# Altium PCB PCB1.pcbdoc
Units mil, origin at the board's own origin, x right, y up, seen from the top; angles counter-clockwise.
Board outline 7744.96 x 4259.33 mil, 2 copper layers (Top Layer, Bottom Layer); 28 components, 7 nets, 68 pads, 56 vias.
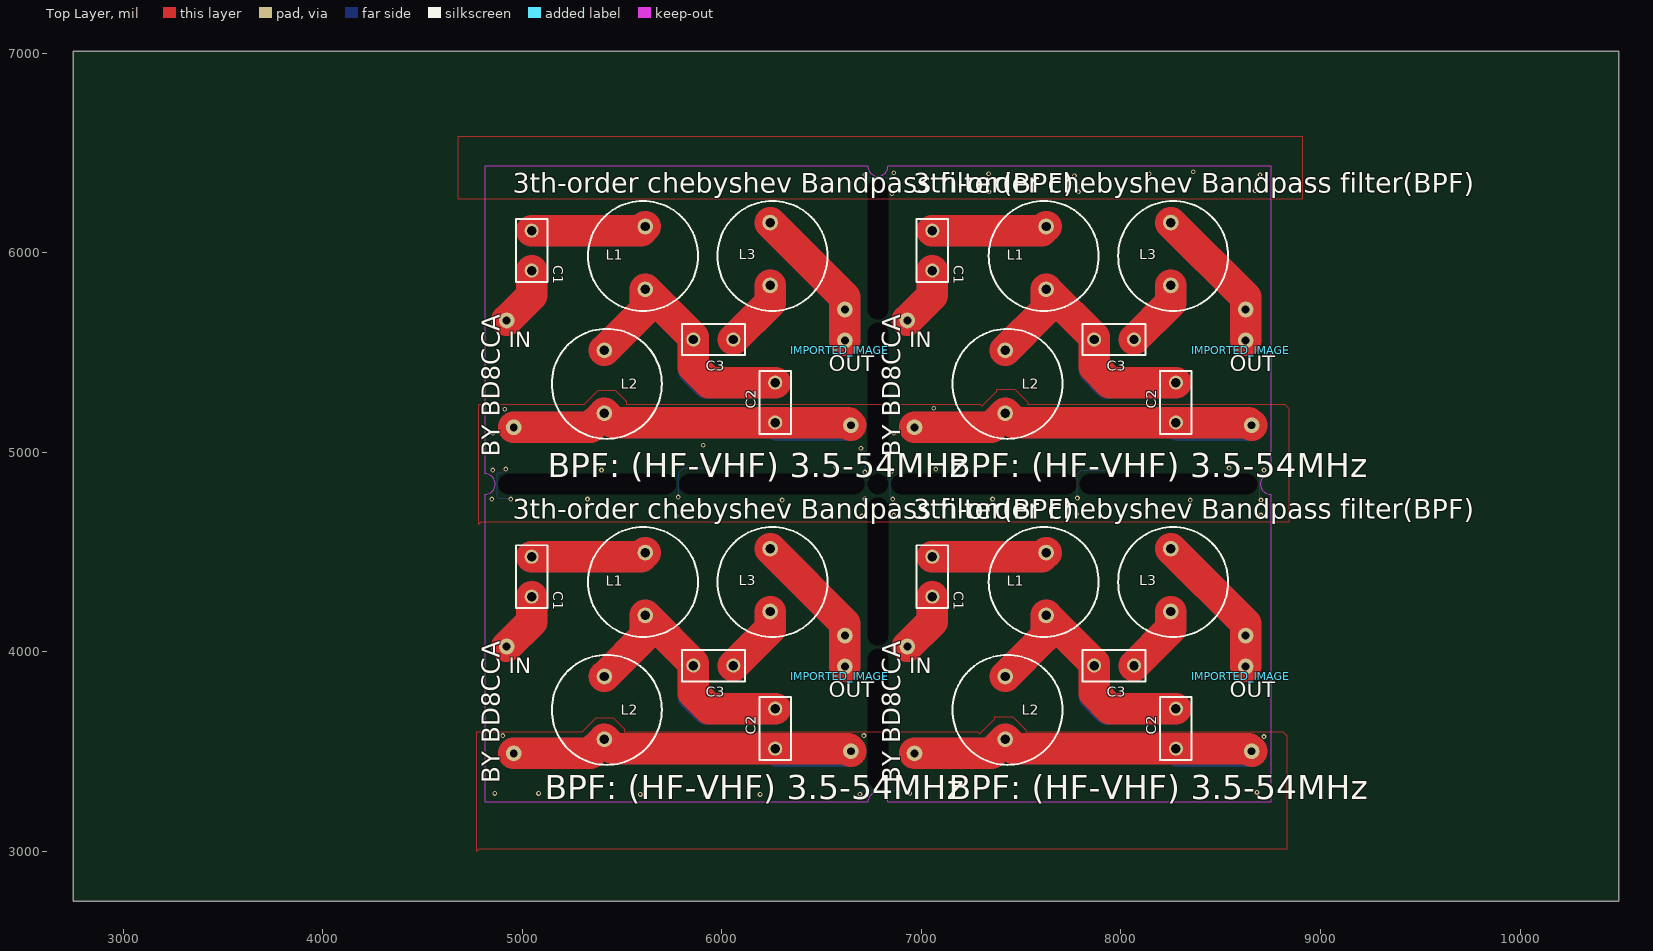
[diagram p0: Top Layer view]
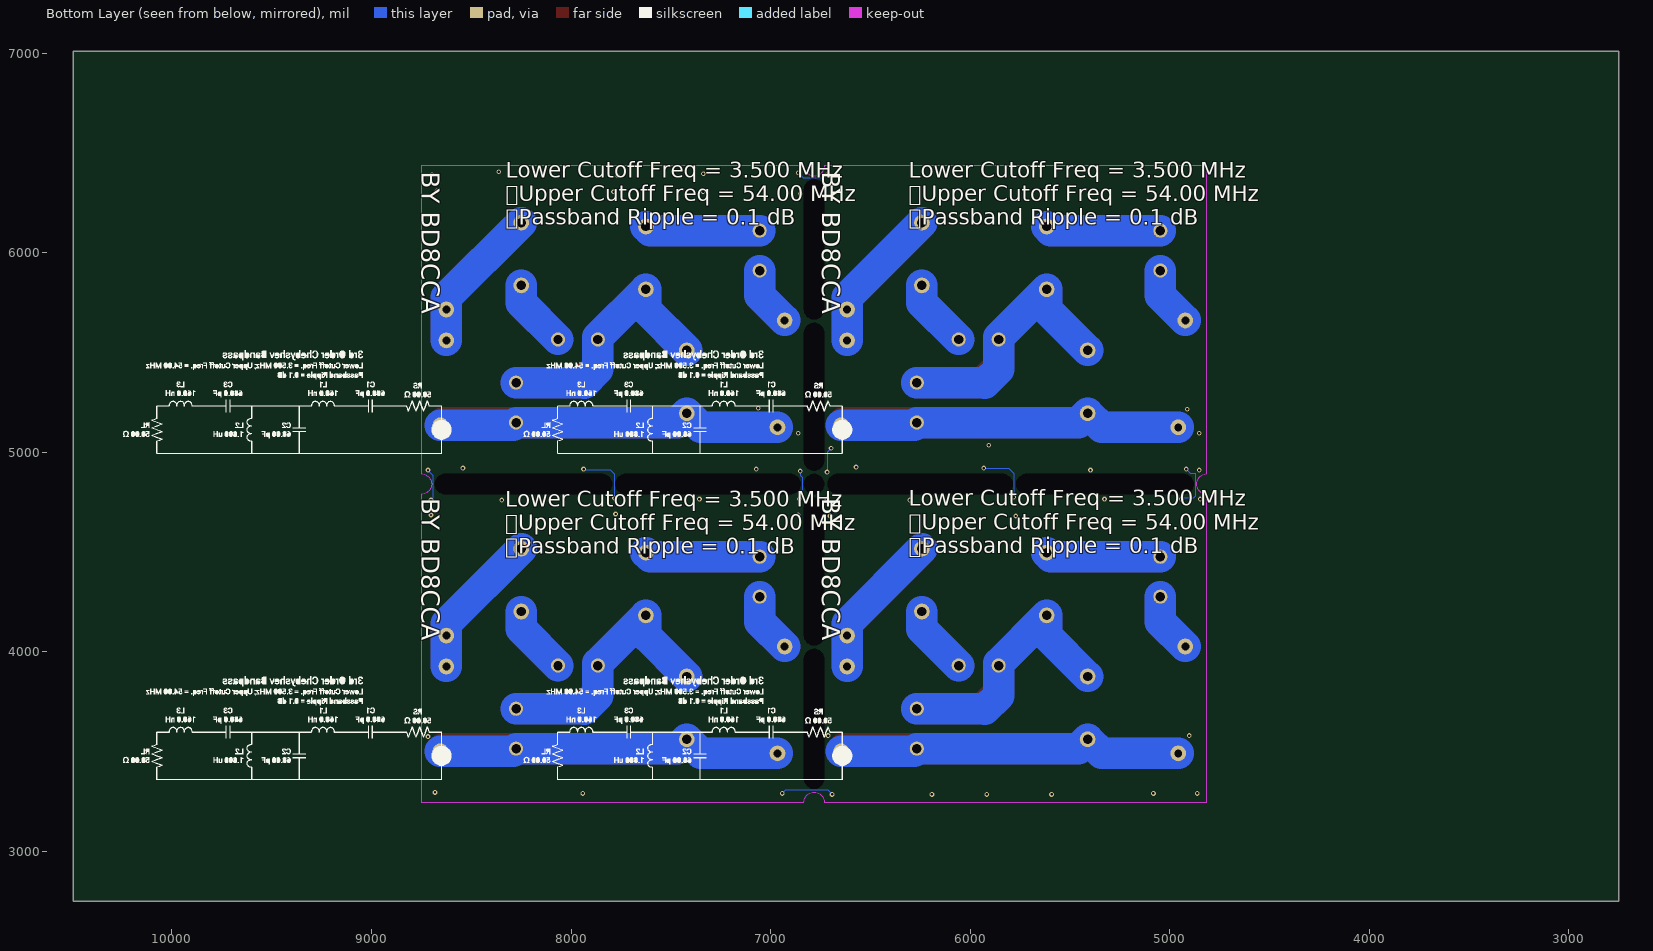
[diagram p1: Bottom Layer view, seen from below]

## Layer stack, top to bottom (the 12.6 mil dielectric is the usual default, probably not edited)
Top Layer: signal copper (thickness not stored)
Dielectric: dielectric 12.6, FR-4, Dk 4.8
Bottom Layer: signal copper (thickness not stored)

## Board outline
10494.96,2750 2750,2750 2750,7009.33 10494.96,7009.33
cut-out: 4931.7,4891.18 ccw(c4931.7,4840) 4880.52,4840 ccw(c4931.7,4840) 4931.7,4788.82 5719.1,4788.82 ccw(c5719.1,4840) 5770.28,4840 ccw(c5719.1,4840) 5719.1,4891.18
cut-out: 5837.21,4891.18 ccw(c5837.21,4840) 5786.03,4840 ccw(c5837.21,4840) 5837.21,4788.82 6663.98,4788.82 ccw(c6663.98,4840) 6715.16,4840 ccw(c6663.98,4840) 6663.98,4891.18
cut-out: 6730.91,6316.38 6730.91,5715.98 ccw(c6782.09,5715.98) 6782.09,5664.8 ccw(c6782.09,5715.98) 6833.27,5715.98 6833.27,6316.38 ccw(c6782.09,6316.38) 6782.09,6367.56 ccw(c6782.09,6316.38)
cut-out: 6730.91,4958.11 ccw(c6782.09,4958.11) 6782.09,4906.93 ccw(c6782.09,4958.11) 6833.27,4958.11 6833.27,5597.87 ccw(c6782.09,5597.87) 6782.09,5649.05 ccw(c6782.09,5597.87) 6730.91,5597.87
cut-out: 6730.91,4082.13 ccw(c6782.09,4082.13) 6782.09,4030.95 ccw(c6782.09,4082.13) 6833.27,4082.13 6833.27,4721.89 ccw(c6782.09,4721.89) 6782.09,4773.07 ccw(c6782.09,4721.89) 6730.91,4721.89
cut-out: 6730.91,4840 ccw(c6782.09,4840) 6782.09,4788.82 ccw(c6782.09,4840) 6833.27,4840 ccw(c6782.09,4840) 6782.09,4891.18 ccw(c6782.09,4840)
cut-out: 7845.08,4891.18 ccw(c7845.08,4840) 7793.9,4840 ccw(c7845.08,4840) 7845.08,4788.82 8632.48,4788.82 ccw(c8632.48,4840) 8683.66,4840 ccw(c8632.48,4840) 8632.48,4891.18
cut-out: 6730.91,3363.62 ccw(c6782.09,3363.62) 6782.09,3312.44 ccw(c6782.09,3363.62) 6833.27,3363.62 6833.27,3964.02 ccw(c6782.09,3964.02) 6782.09,4015.2 ccw(c6782.09,3964.02) 6730.91,3964.02
cut-out: 6900.2,4891.18 ccw(c6900.2,4840) 6849.02,4840 ccw(c6900.2,4840) 6900.2,4788.82 7726.97,4788.82 ccw(c7726.97,4840) 7778.15,4840 ccw(c7726.97,4840) 7726.97,4891.18

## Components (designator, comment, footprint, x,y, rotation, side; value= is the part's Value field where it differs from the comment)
C1 "CT81-M7Y5P1B821KSE" CAP-TH_L8.0-W4.0-P5.00-D1.2 5047.09,6010 r270 top
C1 "CT81-M7Y5P1B821KSE" CAP-TH_L8.0-W4.0-P5.00-D1.2 7054.96,6010 r270 top
C1 "CT81-M7Y5P1B821KSE" CAP-TH_L8.0-W4.0-P5.00-D1.2 5047.09,4376.15 r270 top
C1 "CT81-M7Y5P1B821KSE" CAP-TH_L8.0-W4.0-P5.00-D1.2 7054.96,4376.14 r270 top
C2 "CT81-M7Y5P1B821KSE" CAP-TH_L8.0-W4.0-P5.00-D1.2 6267.84,5248.41 r90 top
C2 "CT81-M7Y5P1B821KSE" CAP-TH_L8.0-W4.0-P5.00-D1.2 8275.71,5248.41 r90 top
C2 "CT81-M7Y5P1B821KSE" CAP-TH_L8.0-W4.0-P5.00-D1.2 6267.84,3614.55 r90 top
C2 "CT81-M7Y5P1B821KSE" CAP-TH_L8.0-W4.0-P5.00-D1.2 8275.71,3614.55 r90 top
C3 "CT81-M7Y5P1B821KSE" CAP-TH_L8.0-W4.0-P5.00-D1.2 5957.84,5564.49 r180 top
C3 "CT81-M7Y5P1B821KSE" CAP-TH_L8.0-W4.0-P5.00-D1.2 7965.71,5564.49 r180 top
C3 "CT81-M7Y5P1B821KSE" CAP-TH_L8.0-W4.0-P5.00-D1.2 5957.84,3930.63 r180 top
C3 "CT81-M7Y5P1B821KSE" CAP-TH_L8.0-W4.0-P5.00-D1.2 7965.71,3930.63 r180 top
IMPORTED_IMAGE "IMPORTED_IMAGE" IMPORTED_IMAGE 6592.09,5510 r0 top
IMPORTED_IMAGE "IMPORTED_IMAGE" IMPORTED_IMAGE 8599.96,5510 r0 top
IMPORTED_IMAGE "IMPORTED_IMAGE" IMPORTED_IMAGE 6592.09,3876.14 r0 top
IMPORTED_IMAGE "IMPORTED_IMAGE" IMPORTED_IMAGE 8599.96,3876.14 r0 top
L1 "直插电感8mm" 直插电感8mm 5617.09,6130.83 r270 top
L1 "直插电感8mm" 直插电感8mm 7624.96,6130.83 r270 top
L1 "直插电感8mm" 直插电感8mm 5617.09,4496.98 r270 top
L1 "直插电感8mm" 直插电感8mm 7624.96,4496.97 r270 top
L2 "直插电感8mm" 直插电感8mm 5412.09,5195 r90 top
L2 "直插电感8mm" 直插电感8mm 7419.96,5195 r90 top
L2 "直插电感8mm" 直插电感8mm 5412.09,3561.14 r90 top
L2 "直插电感8mm" 直插电感8mm 7419.96,3561.14 r90 top
L3 "直插电感8mm" 直插电感8mm 6242.09,5835.55 r90 top
L3 "直插电感8mm" 直插电感8mm 8249.96,5835.55 r90 top
L3 "直插电感8mm" 直插电感8mm 6242.09,4201.69 r90 top
L3 "直插电感8mm" 直插电感8mm 8249.96,4201.69 r90 top

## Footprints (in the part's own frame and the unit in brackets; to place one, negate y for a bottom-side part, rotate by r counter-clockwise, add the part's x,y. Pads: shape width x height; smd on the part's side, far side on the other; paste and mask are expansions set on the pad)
CAP-TH_L8.0-W4.0-P5.00-D1.2 [mm]
  round 1.8 hole 1.2 mask+0.051: 1(-2.54,0) 2(2.54,0)
  silkscreen extent -4,-2 4,2
IMPORTED_IMAGE [mil]
直插电感8mm [mm]
  round 2 hole 1.2 paste+0 mask+0.102: 1(0,0) 2(8,0)
  silkscreen extent -3.25,-7.3 10.75,6.7

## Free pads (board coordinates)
  round 78.74 hole 39.37 mask+2.01: 3(4922.09,4026.14) 3(4922.09,5660) 3(6617.09,3926.14) 3(6617.09,4081.14) 3(6617.09,5560) 3(6617.09,5715) 3(6929.96,4026.14) 3(6929.96,5660) 3(8624.96,3926.14) 3(8624.96,4081.14) 3(8624.96,5560) 3(8624.96,5715) 4(4957.84,3490.63) 4(4957.84,5124.49) 4(6647.09,3501.14) 4(6647.09,5135) 4(6965.71,3490.63) 4(6965.71,5124.49) 4(8654.96,3501.14) 4(8654.96,5135)

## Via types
v1: diameter 24.02, hole 12.01, Top Layer to Bottom Layer, 56 vias

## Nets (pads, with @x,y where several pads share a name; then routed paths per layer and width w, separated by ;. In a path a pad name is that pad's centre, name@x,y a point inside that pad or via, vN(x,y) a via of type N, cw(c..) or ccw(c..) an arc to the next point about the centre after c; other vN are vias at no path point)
$1N347: C1.1 L1.1 | length 4629
  Top Layer w157.5: C1.1@5047.09,4476.15 5596.26,4476.15 L1.1@5617.09,4496.98 ; C1.1@5047.09,6110 5596.26,6110 L1.1@5617.09,6130.83 ; C1.1@7054.96,4476.14 7604.13,4476.14 L1.1@7624.96,4496.97 ; C1.1@7054.96,6110 7604.13,6110 L1.1@7624.96,6130.83
  Bottom Layer w157.5: C1.1@5047.09,4476.15 5596.26,4476.15 L1.1@5617.09,4496.98 ; C1.1@5047.09,6110 5596.26,6110 L1.1@5617.09,6130.83 ; C1.1@7054.96,4476.14 7604.13,4476.14 L1.1@7624.96,4496.97 ; C1.1@7054.96,6110 7604.13,6110 L1.1@7624.96,6130.83
$1N349: C3.1 L3.1 | length 2779
  Top Layer w157.5: C3.1@6057.84,3930.63 6242.09,4114.88 L3.1@6242.09,4201.69 ; C3.1@6057.84,5564.49 6242.09,5748.74 L3.1@6242.09,5835.55 ; C3.1@8065.71,3930.63 8249.96,4114.88 L3.1@8249.96,4201.69 ; C3.1@8065.71,5564.49 8249.96,5748.74 L3.1@8249.96,5835.55
  Bottom Layer w157.5: C3.1@6057.84,3930.63 6242.09,4114.88 L3.1@6242.09,4201.69 ; C3.1@6057.84,5564.49 6242.09,5748.74 L3.1@6242.09,5835.55 ; C3.1@8065.71,3930.63 8249.96,4114.88 L3.1@8249.96,4201.69 ; C3.1@8065.71,5564.49 8249.96,5748.74 L3.1@8249.96,5835.55
$1N351: C2.2 C3.2 L1.2 L2.2 | length 10615.4
  Top Layer w157.5: L2.2@5412.09,3876.11 5617.09,4081.11 5617.09,4182.02 5857.84,3941.26 5857.84,3930.63 5857.84,3793.8 5937.09,3714.55 C2.2@6267.84,3714.55 ; L2.2@5412.09,5509.96 5617.09,5714.96 5617.09,5815.87 5857.84,5575.12 5857.84,5564.49 5857.84,5427.66 5937.09,5348.41 C2.2@6267.84,5348.41 ; L2.2@7419.96,3876.1 7624.96,4081.1 7624.96,4182.01 7865.71,3941.26 7865.71,3930.63 7865.71,3793.8 7944.96,3714.55 C2.2@8275.71,3714.55 ; L2.2@7419.96,5509.96 7624.96,5714.96 7624.96,5815.87 7865.71,5575.12 7865.71,5564.49 7865.71,5427.66 7944.96,5348.41 C2.2@8275.71,5348.41
  Bottom Layer w157.5: L2.2@5412.09,3876.11 5617.09,4081.11 5617.09,4182.02 5857.84,3941.26 5857.84,3930.63 5857.84,3780.39 5927.09,3711.14 5930.5,3714.55 C2.2@6267.84,3714.55 ; L2.2@5412.09,5509.96 5617.09,5714.96 5617.09,5815.87 5857.84,5575.12 5857.84,5564.49 5857.84,5414.25 5927.09,5345 5930.5,5348.41 C2.2@6267.84,5348.41 ; L2.2@7419.96,3876.1 7624.96,4081.1 7624.96,4182.01 7865.71,3941.26 7865.71,3930.63 7865.71,3780.39 7934.96,3711.14 7938.37,3714.55 C2.2@8275.71,3714.55 ; L2.2@7419.96,5509.96 7624.96,5714.96 7624.96,5815.87 7865.71,5575.12 7865.71,5564.49 7865.71,5414.25 7934.96,5345 7938.37,5348.41 C2.2@8275.71,5348.41
GND: C2.1 L2.1 pad.4 | length 15625.9
  Top Layer w157.5: pad.4@4957.84,3490.63 5341.58,3490.63 5412.09,3561.14 5458.68,3514.55 6267.84,3514.55 6633.68,3514.55 pad.4@6647.09,3501.14 ; pad.4@4957.84,5124.49 5341.58,5124.49 5412.09,5195 5458.68,5148.41 6267.84,5148.41 6633.68,5148.41 pad.4@6647.09,5135 ; pad.4@6965.71,3490.63 7349.45,3490.63 7419.96,3561.14 7466.55,3514.55 8275.71,3514.55 8641.55,3514.55 pad.4@8654.96,3501.14 ; pad.4@6965.71,5124.49 7349.45,5124.49 7419.96,5195 7466.55,5148.41 8275.71,5148.41 8641.55,5148.41 pad.4@8654.96,5135
  Bottom Layer w5: v1(4917.09,4915) 4897.09,4895 4872.09,4895 4872.09,4780 4882.09,4770 4937.09,4770 v1(4942.09,4765) ; v1(5782.09,4775) 5782.09,4895 5807.09,4920 v1(5932.09,4920) ; v1(6692.09,3285) 6712.09,3305 6927.09,3305 v1(6942.09,3290) ; v1(6697.09,5020) 6717.09,5000 v1(6717.09,4900) ; v1(6717.09,6390) 6732.09,6375 6837.09,6375 v1(6862.09,6400) ; v1(6852.09,4905) 6852.09,4885 6842.09,4875 6842.09,4780 v1(6857.09,4765) ; v1(7782.09,4770) 7782.09,4890 7802.09,4910 7932.09,4910 v1(7937.09,4915) ; v1(8702.09,4760) 8692.09,4770 8692.09,4885 v1(8717.09,4910)
  Bottom Layer w157.5: pad.4@4957.84,3490.63 5341.58,3490.63 5412.09,3561.14 5458.68,3514.55 6267.84,3514.55 6281.25,3501.14 pad.4@6647.09,3501.14 ; pad.4@4957.84,5124.49 5341.58,5124.49 5412.09,5195 5458.68,5148.41 6267.84,5148.41 6281.25,5135 pad.4@6647.09,5135 ; pad.4@6965.71,3490.63 7349.45,3490.63 7419.96,3561.14 7466.55,3514.55 8275.71,3514.55 8289.12,3501.14 pad.4@8654.96,3501.14 ; pad.4@6965.71,5124.49 7349.45,5124.49 7419.96,5195 7466.55,5148.41 8275.71,5148.41 8289.12,5135 pad.4@8654.96,5135
  other v1: 5592.09,3285 5917.09,3285 6192.09,3285 4862.09,3290 5082.09,3290 7942.09,3290 8682.09,3295 8717.09,3575 4902.09,3580 6712.09,3580 5772.09,4680 6702.09,4680 6862.09,4685 8702.09,4685 7777.09,4690 6302.09,4760 8347.09,4760 4847.09,4765 5327.09,4765 6717.09,4765 7357.09,4765 4852.09,4910 5397.09,4910 7072.09,4915 8542.09,4920 6572.09,4925 5907.09,5035 4852.09,5095 6862.09,5095 4912.09,5215 7062.09,5220 6852.09,6295 7338.57,6305 7787.09,6305 8672.09,6310 7767.09,6385 8697.09,6390 7337.09,6395 8142.09,6395 8362.09,6405
IN: C1.2 pad.3@4922.09,4026.14 pad.3@4922.09,5660 pad.3@6929.96,4026.14 pad.3@6929.96,5660 | length 2414.2
  Top Layer w157.5: pad.3@4922.09,4026.14 5047.09,4151.15 C1.2@5047.09,4276.15 ; pad.3@4922.09,5660 5047.09,5785 C1.2@5047.09,5910 ; pad.3@6929.96,4026.14 7054.96,4151.14 C1.2@7054.96,4276.14 ; pad.3@6929.96,5660 7054.96,5785 C1.2@7054.96,5910
  Bottom Layer w157.5: pad.3@4922.09,4026.14 5047.09,4151.15 C1.2@5047.09,4276.15 ; pad.3@4922.09,5660 5047.09,5785 C1.2@5047.09,5910 ; pad.3@6929.96,4026.14 7054.96,4151.14 C1.2@7054.96,4276.14 ; pad.3@6929.96,5660 7054.96,5785 C1.2@7054.96,5910
OUT: L3.2 pad.3@6617.09,3926.14 pad.3@6617.09,4081.14 pad.3@6617.09,5560 pad.3@6617.09,5715 pad.3@8624.96,3926.14 pad.3@8624.96,4081.14 pad.3@8624.96,5560 pad.3@8624.96,5715 | length 5966.7
  Top Layer w157.5: L3.2@6242.09,4516.65 6617.09,4141.65 6617.09,4081.14 pad.3@6617.09,3926.14 ; L3.2@6242.09,6150.51 6617.09,5775.51 6617.09,5715 pad.3@6617.09,5560 ; L3.2@8249.96,4516.65 8624.96,4141.65 8624.96,4081.14 pad.3@8624.96,3926.14 ; L3.2@8249.96,6150.51 8624.96,5775.51 8624.96,5715 pad.3@8624.96,5560
  Bottom Layer w157.5: L3.2@6242.09,4516.65 6617.09,4141.65 6617.09,4081.14 pad.3@6617.09,3926.14 ; L3.2@6242.09,6150.51 6617.09,5775.51 6617.09,5715 pad.3@6617.09,5560 ; L3.2@8249.96,4516.65 8624.96,4141.65 8624.96,4081.14 pad.3@8624.96,3926.14 ; L3.2@8249.96,6150.51 8624.96,5775.51 8624.96,5715 pad.3@8624.96,5560
"": 

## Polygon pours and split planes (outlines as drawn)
GND on Top Layer (solid, pour order 2): 4677.09,6270 8912.09,6270 8912.09,6580 4677.09,6580
GND on Top Layer (solid, remove dead copper, pour order 0): 4782.09,5240 5312.09,5240 5382.09,5310 5467.09,5310 5522.09,5255 5522.09,5240 7292.09,5240 7302.09,5230 7377.09,5305 7377.09,5315 7467.09,5315 7532.09,5250 7532.09,5240 8822.09,5240 8842.09,5220 8842.09,4650 4792.09,4650 4782.09,4640
GND on Top Layer (solid, remove dead copper, pour order 1): 4772.09,3600 5302.09,3600 5372.09,3670 5457.09,3670 5512.09,3615 5512.09,3600 7282.09,3600 7292.09,3590 7367.09,3665 7367.09,3675 7457.09,3675 7522.09,3610 7522.09,3600 8812.09,3600 8832.09,3580 8832.09,3010 4782.09,3010 4772.09,3000

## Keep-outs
Board Outline Layer:
  lines w3.94 net "": 4813.59,3245.51 6730.91,3245.51 cw(c6782.09,3245.51) 6782.09,3296.7 cw(c6782.09,3245.51) 6833.27,3245.51 8750.59,3245.51 8750.59,4788.82 cw(c8750.59,4840) 8699.41,4840 cw(c8750.59,4840) 8750.59,4891.18 8750.59,6434.48 6833.27,6434.48 cw(c6782.09,6434.48) 6782.09,6383.3 cw(c6782.09,6434.48) 6730.91,6434.48 4813.59,6434.48 4813.59,4891.18 cw(c4813.59,4840) 4864.77,4840 cw(c4813.59,4840) 4813.59,4788.82 4813.59,3245.51

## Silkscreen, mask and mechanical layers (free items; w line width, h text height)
Top Silkscreen Layer:
  text "3th-order chebyshev Bandpass filter(BPF)" at 4952.09,6300 h98.43
  text "3th-order chebyshev Bandpass filter(BPF)" at 6959.96,6300 h98.43
  text "IN" at 4932.09,5525 h78.74
  text "IN" at 6939.96,5525 h78.74
  text "OUT" at 6537.09,5405 h78.74
  text "OUT" at 8544.96,5405 h78.74
  text "BY BD8CCA" at 4887.59,4975.87 h89.16 r90
  text "BY BD8CCA" at 6895.46,4975.87 h89.16 r90
  text "BPF: (HF-VHF) 3.5-54MHz" at 5127.09,4875 h120
  text "BPF: (HF-VHF) 3.5-54MHz" at 7134.96,4875 h120
  text "3th-order chebyshev Bandpass filter(BPF)" at 4952.09,4666.15 h98.43
  text "3th-order chebyshev Bandpass filter(BPF)" at 6959.96,4666.14 h98.43
  text "IN" at 4932.09,3891.14 h78.74
  text "IN" at 6939.96,3891.14 h78.74
  text "OUT" at 6537.09,3771.14 h78.74
  text "OUT" at 8544.96,3771.14 h78.74
  text "BY BD8CCA" at 4887.59,3342.01 h89.16 r90
  text "BY BD8CCA" at 6895.46,3342.01 h89.16 r90
  text "BPF: (HF-VHF) 3.5-54MHz" at 5112.09,3260 h120
  text "BPF: (HF-VHF) 3.5-54MHz" at 7137.09,3260 h120
Bottom Silkscreen Layer:
  text "BY BD8CCA" at 6741.58,6404.13 h89.16 r90
  text "BY BD8CCA" at 8749.45,6404.13 h89.16 r90
  text "Lower Cutoff Freq = 3.500 MHz /  Upper Cutoff Freq = 54.00 MHz /  Passband Ripple = 0.1 dB" at 6307.09,6140 h78.74
  text "Lower Cutoff Freq = 3.500 MHz /  Upper Cutoff Freq = 54.00 MHz /  Passband Ripple = 0.1 dB" at 8326.77,6140 h78.74
  text "BY BD8CCA" at 6741.58,4770.28 h89.16 r90
  text "BY BD8CCA" at 8749.45,4770.28 h89.16 r90
  text "Lower Cutoff Freq = 3.500 MHz /  Upper Cutoff Freq = 54.00 MHz /  Passband Ripple = 0.1 dB" at 6307.09,4494.33 h78.74
  text "Lower Cutoff Freq = 3.500 MHz /  Upper Cutoff Freq = 54.00 MHz /  Passband Ripple = 0.1 dB" at 8330.59,4490.52 h78.74
Mechanical Layer:
  lines w1 net "": 4880.52,4840 cw(c4931.7,4840) 4931.7,4891.18 5719.1,4891.18 cw(c5719.1,4840) 5770.28,4840 cw(c5719.1,4840) 5719.1,4788.82 4931.7,4788.82 cw(c4931.7,4840) 4880.52,4840 ; 5786.03,4840 cw(c5837.21,4840) 5837.21,4891.18 6663.98,4891.18 cw(c6663.98,4840) 6715.16,4840 cw(c6663.98,4840) 6663.98,4788.82 5837.21,4788.82 cw(c5837.21,4840) 5786.03,4840 ; 6730.91,3363.62 ccw(c6782.09,3363.62) 6782.09,3312.44 ccw(c6782.09,3363.62) 6833.27,3363.62 6833.27,3964.02 ccw(c6782.09,3964.02) 6782.09,4015.2 ccw(c6782.09,3964.02) 6730.91,3964.02 6730.91,3363.62 ; 6730.91,4082.13 ccw(c6782.09,4082.13) 6782.09,4030.95 ccw(c6782.09,4082.13) 6833.27,4082.13 6833.27,4721.89 ccw(c6782.09,4721.89) 6782.09,4773.07 ccw(c6782.09,4721.89) 6730.91,4721.89 6730.91,4082.13 ; 6730.91,4840 ccw(c6782.09,4840) 6782.09,4788.82 ccw(c6782.09,4840) 6833.27,4840 ccw(c6782.09,4840) 6782.09,4891.18 ccw(c6782.09,4840) 6730.91,4840 ; 6730.91,4958.11 ccw(c6782.09,4958.11) 6782.09,4906.93 ccw(c6782.09,4958.11) 6833.27,4958.11 6833.27,5597.87 ccw(c6782.09,5597.87) 6782.09,5649.05 ccw(c6782.09,5597.87) 6730.91,5597.87 6730.91,4958.11 ; 6730.91,5715.98 6730.91,6316.38 cw(c6782.09,6316.38) 6782.09,6367.56 cw(c6782.09,6316.38) 6833.27,6316.38 6833.27,5715.98 cw(c6782.09,5715.98) 6782.09,5664.8 cw(c6782.09,5715.98) 6730.91,5715.98 ; 6849.02,4840 cw(c6900.2,4840) 6900.2,4891.18 7726.97,4891.18 cw(c7726.97,4840) 7778.15,4840 cw(c7726.97,4840) 7726.97,4788.82 6900.2,4788.82 cw(c6900.2,4840) 6849.02,4840 ; 7793.9,4840 cw(c7845.08,4840) 7845.08,4891.18 8632.48,4891.18 cw(c8632.48,4840) 8683.66,4840 cw(c8632.48,4840) 8632.48,4788.82 7845.08,4788.82 cw(c7845.08,4840) 7793.9,4840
